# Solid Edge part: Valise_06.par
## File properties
Author: Bernard DUMAS
Template: Normal.par
Last saved by: FR026244
Revision: 14
Application: Solid Edge
Material: Bois, Frêne
Style de face: Jaune kaki
Style de remplissage: Liège
Style virtuel: Frêne verni
Coef. of Thermal Exp: 0.0
Thermal Conductivity: 0.0
Specific Heat: 0.0
Modulus of Elasticity: 0.0
Poission's Ratio: 0.0
Yield Stress: 0.0
Ultimate Stress: 0.0
Elongation: 0.0
Densité: 460.000 kg/m^3
Précision: 0.9900
Document Number: 06
Revision: a
Project Name: Slamson
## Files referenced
..\Valise_Salmson.asm
bD:\Documents and Settings\FR026244\Mes Documents\Bernard\Slamson\Valise-Salmson\Valise_Salmson.asm
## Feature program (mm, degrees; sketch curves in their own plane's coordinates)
sketch for "unnamed Protrusion 1" plane through (0, 0, 0) normal (0, -1, 0) x-axis (1, 0, 0)
extrude "unnamed Protrusion 1" add to key point symmetric
extrude "unnamed Cutout 1" cut finite 6
extrude "Enlèvement_matière_2" cut finite 6
fillet "Congé_1" radius 3
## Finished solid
Body 1: solid body, 12 faces, 27 edges, 18 vertices.
  Faces by surface: plane 10, cylinder 2
  Edges by curve: line 23, circle 4
Bounding box of the edges (mm): 426.500 x 850.000 x 6.000, from (0, -425, 157) to (426.5, 425, 163).
Cylindrical faces by radius (mm): R3 x2
Planar faces by outward normal: +y 2, +z 1, -x 1, -y 2, -z 2, oblique 2
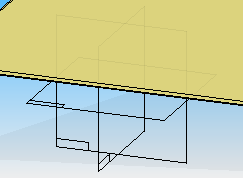
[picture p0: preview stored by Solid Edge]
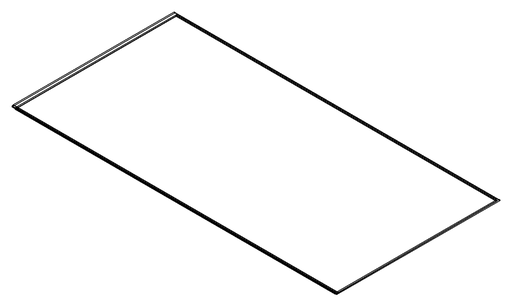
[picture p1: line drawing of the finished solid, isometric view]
